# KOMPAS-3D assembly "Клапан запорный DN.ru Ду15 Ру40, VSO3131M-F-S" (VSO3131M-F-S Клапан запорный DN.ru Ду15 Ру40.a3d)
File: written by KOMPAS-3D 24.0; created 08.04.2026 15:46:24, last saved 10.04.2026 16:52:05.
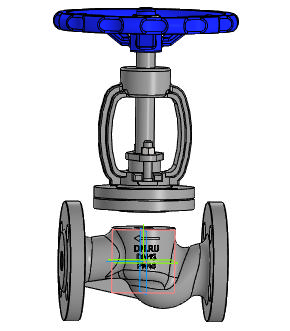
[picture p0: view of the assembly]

Document properties: Автор: R2D2; Полное имя файла: E:\Работа\Зайцев\VSO3131M-F-S Клапан запорный DN.ru Ду15-100 Ру40\DN15\исходные материалы\VSO3131M-F-S Клапан запорный DN.ru Ду15 Ру40.a3d

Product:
- Component [detail]: Клапан запорный DN.ru Ду15 Ру16  | designation VSO1121M-F-S  | qty 1  | pos. 1  | Масса: 3.1; Раздел спецификации: Прочие изделия; Примечание: D090-01942; Автор: R2D2; source file: 1.m3d
- Component [detail]: Клапан запорный DN.ru Ду15 Ру16  | designation VSO1121M-F-S  | qty 1  | Масса: 3.1; Раздел спецификации: Прочие изделия; Примечание: D090-01942; Автор: R2D2; source file: 2.m3d
- Component [standard]: Фланец 15-1-01-1-B-ВЧ40-I-dв 19 ГОСТ 33259-2015  | qty 2  | Материал: ВЧ40 ГОСТ 7293-85 (density 7200 kg/m3); Масса: 0.29; Раздел спецификации: Стандартные изделия; additional columns: BOSimple***Material:38d6725a-5efe-48e1-b177-a7817acb862a
- Part/product: Клапан запорный DN.ru Ду15 Ру40  | designation VSO3131M-F-S
    Масса: 3.77
    Раздел спецификации: Прочие изделия
    Примечание: D090-02137

Expressions: D090-01942
Referenced files in E:\Работа\Зайцев\VSO3131M-F-S Клапан запорный DN.ru Ду15-100 Ру40\DN15\исходные материалы\: 1.m3d, 2.m3d
Referenced files in C:\Program Files\ASCON\KOMPAS-3D v24\Libs\PolynomLib\DATA\vault\Methods\Kompas\3D\: PLib_Flange_GOST_33259_1401.m3d
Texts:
  VSO1121M-F-S
  Фланцы ГОСТ Р 54432
  ВЧ40
  BOSimple***PART:3f5f0d7e-d4da-47dc-6145-6a7f26b7079a***SHORTLOC:B6A6_23E38AE8DB154823[I;1;Круглый;15;1;19;0;ВЧ40 ГОСТ 7293-85]
  BOSimple***Material:38d6725a-5efe-48e1-b177-a7817acb862a
  Программные изделия  и базы данных
  VSO3131M-F-S
  VSO1121M-F-S Клапан запорный DN.ru Ду15 Ру16
  Фланец 15-1-01-1-B-ВЧ40-I-dв 19 ГОСТ 33259-2015 (1)
  Ch34
  Фланец 15-1-01-1-B-ВЧ40-I-dв 19 ГОСТ 33259-2015 (2)
  Ось Z.Начало координат
  Ось Y.Начало координат
  Плоскость ZY.Начало координат
  Плоскость ZX.Начало координат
